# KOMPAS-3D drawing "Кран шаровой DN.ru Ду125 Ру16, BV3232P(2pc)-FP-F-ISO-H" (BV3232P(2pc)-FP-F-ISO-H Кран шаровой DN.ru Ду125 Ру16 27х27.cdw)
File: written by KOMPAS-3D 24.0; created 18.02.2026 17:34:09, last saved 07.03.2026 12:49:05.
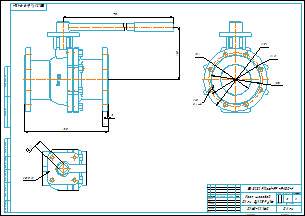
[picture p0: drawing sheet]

Document properties: Автор: R2D2; Форматы листов документа: A2; Полное имя файла: BV3232P(2pc)-FP-F-ISO-H Кран шаровой DN.ru Ду125 Ру16.cdw; Масса: 32; Наименование: Кран шаровой DN.ru Ду125 Ру16; Количество листов документа: 1; Примечание: D160-22160

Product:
- Part/product: Кран шаровой DN.ru Ду125 Ру16  | designation BV3232P(2pc)-FP-F-ISO-H
    Масса: 32
    Раздел спецификации: Прочие изделия
    Форматы листов документа: A2
    Примечание: D160-22160

Views: Проекционный вид 2, Проекционный вид 3
Referenced files in E:\Работа\Зайцев\BV3232P(2pc)-FP-F-ISO-H Кран шаровой DN.ru Ду15-300 Ру16-40\DN125 PN16\: BV3232P(2pc)-FP-F-ISO-H Кран шаровой DN.ru Ду125 Ру16.m3d
Referenced files in E:\Работа\Зайцев\Для компаса\: чертеж DN.ru А3.cdt
Referenced files in E:\Работа\Зайцев\BV3232P(2pc)-FP-F-ISO-H Кран шаровой DN.ru Ду15-300 Ру16-40\DN125 PN16 27х27\: BV3232P(2pc)-FP-F-ISO-H Кран шаровой DN.ru Ду125 Ру16 27х27.m3d
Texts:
  BV3232P(2pc)-FP-F-ISO-H
  ISO 5211
  чертеж DN.ru А3.cdt
  Кран шаровой
  DN.ru Ду125 Ру16
  Кран шаровой DN.ru Ду125 Ру16
  BV3232P(2pc)-FP-F-ISO-H Кран шаровой DN.ru Ду125 Ру16
Dimensions and other numbers on the sheet: 0; 3; 4; 250; 210; 190; 122; 18; 8 отв.; 27; 1:2; 1; 2; 32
